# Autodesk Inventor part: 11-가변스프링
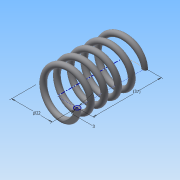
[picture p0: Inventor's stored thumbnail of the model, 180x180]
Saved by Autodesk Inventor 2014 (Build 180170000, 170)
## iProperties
Created: 2015-09
Part Number: 11-가변스프링
Material: 강철, 탄소
Document SubType Name: Modeling
Designer: study
Density: 7.87 g/cm^3
Appearance: 반연마
Mass: 18.8544 g
Surface Area: 32.5077 cm^2
Volume: 2.39574 cm^3
Author: study
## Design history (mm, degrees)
sketch "스케치1"
  geometry: L1 (0, 0)-(11, 0); L2 (11, 0)-(11, 39.945); L3 (11, 39.945)-(0, 39.945); L4 (0, 39.945)-(0, 0); C1 r 1.5 at (11, 0)
  constraints: 8 end point, 2 parallel, 1 centre point, 1 coincident, 1 horizontal, 1 perpendicular
  dimensions: "d0" = 3 diameter of C1; "d1" = 22 diameter of L2 L4; "d2" = 39.9455 distance of L1.end L2.end (derived)
feature "코일1" pitch "d3" = 10; turns "d5" = 5; dims "d4" = 39.9455 (= d2), "d6" = 0, angle "d7" = 90 deg, angle "d8" = 90 deg, "d9" = 0, "d10" = 0
node "작업 평면1"
sketch "스케치2"
  geometry: L1 (-12.5, 0)-(-9.5, 0) reference; L2 (-12.5, 0)-(-9.5, 0) reference; 1 further point
  constraints: 2 horizontal alignment
extrude "돌출1" cut sketch "스케치2" stored distance "d12" = 10; taper "d13" = 0 deg
node "작업 평면2"
sketch "스케치3"
  geometry: L1 (-9.5, 0)-(-12.5, 0) reference; 1 further point
  constraints: 1 horizontal alignment
extrude "돌출2" cut sketch "스케치3" stored distance "d15" = 10; taper "d16" = 0 deg
node "솔리드1"
node "절단 모서리 투영1"
node "절단 모서리 투영2"
node "절단 모서리 투영3"
other parameters: "d11" = 0, "d14" = 39.9455 (= d2)
